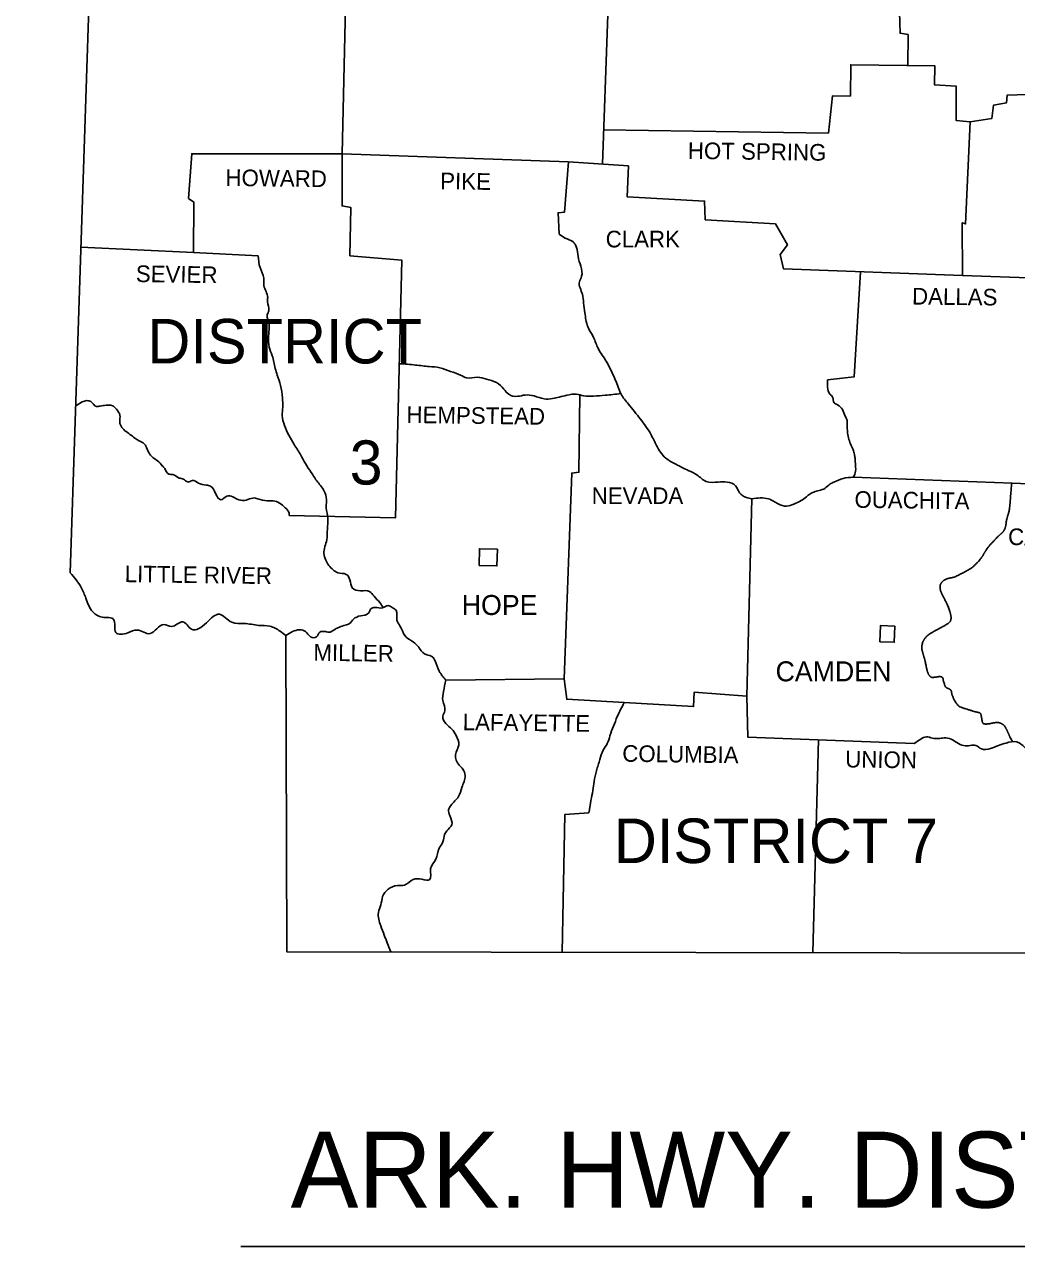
# Model space of a CAD drawing. Extents: x -819161 to 80911, y -6604 to 768454.
# Drawn here: x 60665 to 62056, y 6165 to 7879 of the extents above; entities that cross this region are included whole.
import ezdxf

# ---------------------------------------------------------------- set-up
doc = ezdxf.new("R2010")
doc.units = 0
doc.layers.add('Default', color=7, linetype='Continuous')

msp = doc.modelspace()

# ---------------------------------------------------------------- linework, layer by layer
at = {"layer": 'Default'}
for p, q in [((60745.8, 7349.6), (60736.7, 7343.9)), ((60968.3, 6164.9), (63373.8, 6164.9))]:
    msp.add_line(p, q, dxfattribs=at)
for points in [[(60664.8, 9505.7), (60778.1, 8595.4), (60729, 7109.7)], [(61270.5, 8258.8), (61269.8, 8034.6), (61242.1, 8034), (61244.6, 8017.8), (61218.2, 8018.1), (61217.6, 8005.9), (61191.7, 8005.9), (61192.3, 7997.5), (61154.4, 7996.3), (61153.4, 7963), (61116.4, 7966.4), (61110.2, 7696.9)], [(61891.6, 8113.9), (61713, 8119.2), (61708, 8048.9), (61488.6, 8050.1), (61475.1, 7682.7)], [(61708, 8048.9), (61780.5, 8042.7), (61782.7, 7973.6), (61773.7, 7970.8), (61772.4, 7934.1), (61844, 7928.8), (61844, 7898.6), (61891.6, 7896.1), (61892.6, 7866.2), (61903.8, 7864.3), (61903.4, 7821)], [(61476.9, 7730.9), (61792, 7726.2), (61798, 7778.5), (61822.9, 7778.1), (61823.5, 7822), (61941.4, 7820.5), (61940.8, 7794), (61971.3, 7791.8), (61971, 7743.9), (61990.9, 7742)], [(61990.9, 7742), (62021.4, 7746.7), (62023.6, 7765.4), (62041.6, 7768.5), (62042.9, 7779.4), (62170.5, 7783.4), (62175.5, 7816.4), (62306.2, 7814.6)], [(61990.9, 7742), (61984.4, 7598.9), (61979.7, 7600.4), (61980, 7526.5)], [(61427.6, 7686), (61110.2, 7696.9), (60899.5, 7697.2), (60894.8, 7634.7), (60902.3, 7629.4), (60902, 7559), (60744.1, 7566.3)], [(61110.2, 7696.9), (61110.2, 7624.1), (61122.3, 7621.9), (61121.1, 7554.1), (61193.9, 7548.2), (61184.9, 7186.5), (61036.1, 7190)], [(61414.6, 7584.3), (61413, 7614.4), (61422, 7615.1), (61427.6, 7686), (61511.6, 7680.1), (61509.8, 7636.9), (61618.4, 7630.9), (61619.3, 7604.8), (61717.7, 7598.9), (61734.5, 7569.3), (61724.2, 7555.9), (61729.2, 7535.7), (61980, 7526.5)], [(60902, 7559), (60992.5, 7554.1)], [(61836.9, 7531.8), (61828.2, 7384.5), (61790.8, 7380.1)], [(61980, 7526.5), (62086.1, 7522.6)], [(61443.5, 7359.2), (61442.2, 7250.6), (61432.3, 7249.4), (61421.4, 6960.9)], [(61826.8, 7243.6), (62049.7, 7235.4), (62225.3, 7228.5)], [(61684.7, 7213.3), (61677.5, 6936.9), (61603.8, 6942.2), (61603.1, 6922), (61505.8, 6927.6)], [(61031.4, 7021.6), (61032.7, 6578.4), (63039.7, 6575)], [(61505.8, 6927.6), (61425.1, 6932.3), (61421.4, 6960.9), (61255.5, 6959.3)], [(61912.5, 6870.3), (61679.1, 6879.1), (61677.5, 6936.9)], [(61778.4, 6875.3), (61770.1, 6577.2)], [(61456.3, 6772.9), (61422.6, 6770.8), (61419, 6577.8)]]:
    msp.add_lwpolyline(points, dxfattribs=at)
for points in [[(61302.2, 7119.9), (61302.8, 7143.3), (61328, 7142.6), (61327.4, 7119.3)], [(61864.3, 7012.9), (61864.9, 7035.6), (61885.1, 7035), (61884.5, 7012.3)]]:
    msp.add_lwpolyline(points, close=True, dxfattribs=at)
for points in [[(61414.6, 7584.3), (61423, 7579), (61433.5, 7574), (61439.1, 7565.9), (61441, 7553.1), (61445, 7539.4), (61446, 7525.4), (61442.9, 7517.7), (61447.2, 7500.2), (61448.8, 7488.1), (61450.7, 7474.1), (61454.7, 7454.8), (61461.9, 7441.7), (61468.4, 7425.9), (61479.3, 7408.4), (61488.9, 7390.1), (61493.3, 7380.4), (61501.4, 7360.2), (61511.6, 7346.2), (61528.5, 7325.3), (61543.1, 7303.9), (61551.2, 7288), (61563.9, 7270.6), (61578.2, 7261.8), (61596.3, 7252.8), (61607.8, 7246.9), (61620.6, 7237.6), (61637.7, 7236.9), (61650.1, 7236.9), (61662, 7231.7), (61667.3, 7222), (61677.2, 7215.2), (61684.7, 7213.3)], [(60992.5, 7554.1), (60995.3, 7537.6), (61000.3, 7522.9), (61000.6, 7512.4), (61005.9, 7495.9), (61005.6, 7490), (61007.5, 7477.5), (61005.3, 7471.3), (61007.8, 7458.2), (61007.5, 7447.9), (61007.2, 7439.9), (61008.1, 7426.2), (61012.2, 7414), (61016.5, 7396.3), (61019.3, 7386.6), (61024, 7372.3), (61026.5, 7354.9), (61027.1, 7342.1), (61026.2, 7330), (61029.6, 7316.3), (61035.5, 7302.6), (61043, 7289.5), (61052.3, 7274.6), (61058.8, 7262.8), (61066.9, 7250.3), (61073.5, 7240.1), (61083.7, 7226.7), (61088.1, 7215.8), (61088.1, 7200.8), (61090.3, 7186.2), (61089.6, 7170.7), (61088.7, 7156), (61084.7, 7136.7), (61087.2, 7127.4), (61097.7, 7113.7), (61104.3, 7109.7), (61115.8, 7107.5), (61121.1, 7099.7), (61124.5, 7088.5), (61136, 7084.5), (61148.8, 7083.5), (61155, 7076.7), (61163.1, 7068), (61168, 7060.7)], [(61190.3, 7402.8), (61213.2, 7401), (61232.5, 7398.8), (61247.1, 7397.2), (61262.4, 7391.9), (61276.4, 7386.9), (61285.1, 7382.9), (61299.7, 7383.8), (61312.5, 7381.3), (61326.5, 7376.4), (61337.1, 7367), (61343.9, 7359.9), (61356.4, 7357.1), (61366.9, 7358.9), (61379.4, 7357.7), (61393.4, 7353.6), (61405.2, 7354), (61414.6, 7356.1), (61425.4, 7358.6), (61438.8, 7360.2), (61449.1, 7357.7), (61462.8, 7357.4), (61479, 7358.6), (61500.9, 7361)], [(61790.8, 7380.1), (61790.8, 7369.8), (61794.2, 7360.2), (61798, 7355.8), (61799.8, 7348.4), (61804.8, 7345.2), (61811.7, 7338.4), (61815.7, 7329.4), (61818.2, 7323.2), (61818.5, 7315.4), (61818.8, 7307.9), (61820.1, 7298.9), (61826.6, 7282.1), (61828.5, 7275.5), (61829.4, 7269.9), (61830, 7260.6), (61829.7, 7249.7), (61826.8, 7243.6)], [(60745.8, 7349.6), (60757.9, 7349.9), (60765.7, 7342.8), (60771, 7343.4), (60779.4, 7344.6), (60788.1, 7344), (60793.7, 7339), (60798.7, 7330.6), (60798.4, 7322.2), (60798.7, 7318.8), (60802.7, 7311.9), (60809.2, 7306.3), (60816.4, 7301.1), (60822.6, 7296.4), (60833.8, 7289.5), (60835.1, 7287.4), (60839.1, 7278.3), (60844.7, 7271.5), (60851.3, 7266.8), (60858.4, 7259.4), (60861.5, 7255.9), (60867.1, 7248.1), (60873, 7247.5), (60881.8, 7242.5), (60887.7, 7241), (60893.9, 7236.9), (60900.4, 7239.1), (60908.8, 7235.4), (60919.7, 7232.6), (60925.9, 7231), (60932.8, 7220.8), (60940.3, 7212), (60948.7, 7217), (60965.5, 7212), (60975.7, 7211.7), (60985.1, 7214.5), (60992.2, 7213.6), (61005.3, 7210.5), (61013.4, 7210.5), (61022.4, 7207.4), (61030.5, 7200.8), (61035.8, 7193.4), (61036.1, 7190)], [(61799.8, 7236.6), (61794.2, 7234.1), (61787.4, 7228.2), (61779, 7225.1), (61771.5, 7222.9), (61761.2, 7216.4), (61754.1, 7210.8), (61743.5, 7206.1), (61733.5, 7203), (61721.4, 7206.4), (61714.9, 7210.2), (61708, 7213.3), (61684.7, 7213.3)], [(61799.8, 7236.6), (61812.6, 7241.9), (61826.8, 7243.6)], [(60729, 7109.7), (60744.5, 7089.1), (60751, 7073.9), (60760.7, 7054.9), (60774.1, 7047.4), (60789.9, 7044.3), (60793.1, 7025.9), (60809.6, 7025.3), (60822.9, 7029.4), (60841, 7024.4), (60860.3, 7037.1), (60871.2, 7034.3), (60886.7, 7040.9), (60899.2, 7030.6), (60920, 7039.6), (60938.4, 7051.5), (60955.8, 7040.3), (60972.9, 7038.7), (60993.2, 7035.9), (61009, 7034.7), (61023.4, 7027.8), (61031.4, 7021.6)], [(61031.4, 7021.6), (61050.4, 7029.7), (61059.1, 7027.2), (61066, 7020), (61074.4, 7019.7), (61078.8, 7026.3), (61086.8, 7027.2), (61093.4, 7026.6), (61100.5, 7030.6), (61106.5, 7033.4), (61114.5, 7036.2), (61120.8, 7038.7), (61126.1, 7044.6), (61136.3, 7049.3), (61147.5, 7053.3), (61150.6, 7058.9), (61156.2, 7061.1), (61167.1, 7060.5), (61174.6, 7063.6), (61180.5, 7060.8), (61185.8, 7057.1), (61187.1, 7043.1), (61191.4, 7035.3), (61198.3, 7021.6), (61207.3, 7014.4), (61216, 7007.3), (61219.1, 7002.9), (61228.8, 6994.5), (61236.8, 6992), (61240.6, 6986.1), (61246.5, 6971.5), (61255.5, 6959.3)], [(61255.5, 6959.3), (61252.4, 6943.2), (61251.5, 6930.4), (61254.3, 6916.1), (61251.5, 6908.6), (61255.8, 6898.3), (61264.2, 6890.3), (61270.1, 6881.5), (61273.9, 6868.5), (61269.2, 6854.5), (61274.5, 6839.8), (61279.5, 6834.2), (61282.6, 6825.2), (61278.2, 6808.7), (61273.6, 6796), (61262.7, 6783.5), (61259.6, 6777.3), (61261.1, 6769.2), (61263.9, 6756.1), (61260.8, 6752.1), (61254, 6742.7), (61251.5, 6732.5), (61246.5, 6723.4), (61241.5, 6707.9), (61234.4, 6694.5), (61233.1, 6679.6), (61221.9, 6679.9), (61209.8, 6679.6), (61197.9, 6671.8), (61187.7, 6671.2), (61174.9, 6665.9), (61167.1, 6655.6), (61164.6, 6644.1), (61161.2, 6633.2), (61164.3, 6614.5), (61169.3, 6601.5), (61173.4, 6590.9), (61178.6, 6578.2)], [(61456.3, 6772.9), (61459.1, 6790.4), (61461.9, 6804.4), (61463.7, 6817.1), (61466.8, 6832.1), (61471.8, 6847.9), (61476.2, 6861), (61482.1, 6870.3), (61485.8, 6881.2), (61490.8, 6894.6), (61496.1, 6908), (61505.8, 6927.6)], [(61912.5, 6870.3), (61921.5, 6876.6), (61929.6, 6879.7), (61938, 6877.8), (61946.4, 6877.2), (61954.2, 6878.1), (61964.1, 6876.3), (61972.2, 6871.6), (61981.6, 6867.5), (61990.9, 6867.5), (61999, 6867.5), (62006.5, 6862.6), (62019.2, 6863.2), (62030.4, 6867.5), (62041.3, 6871), (62056.3, 6872.5), (62069, 6863.5), (62078.7, 6855.7), (62086.1, 6847), (62091.7, 6837), (62098, 6831.4), (62107.6, 6827.7), (62115.4, 6825.8), (62124.4, 6823.3), (62129.4, 6820.9), (62133.8, 6810.9), (62140.9, 6796.3), (62154.9, 6791.6), (62171.4, 6798.1), (62185.4, 6801.9), (62195.4, 6805), (62201, 6807.2), (62206.6, 6808.1), (62205.3, 6809), (62211.6, 6810.6), (62217.8, 6806.2), (62221.5, 6800.3), (62228.1, 6791.3), (62234, 6783.8), (62239.9, 6781.3), (62246.4, 6784.4), (62254.2, 6781.6), (62261.4, 6779.2), (62269.8, 6776.7), (62276.6, 6776.4), (62286.3, 6774.2), (62293.1, 6770.1), (62299.6, 6766.1), (62306.5, 6759.2), (62313, 6748), (62315.2, 6739.3), (62322.7, 6730.6), (62330.1, 6730.6), (62340.1, 6716.6), (62344.1, 6711), (62352.2, 6701.4), (62358.1, 6701), (62369.9, 6699.2)]]:
    msp.add_spline(points, degree=3, dxfattribs=at)
msp.add_open_spline([(62049, 7235.4), (62048.1, 7224.2), (62047.2, 7213), (62046.3, 7201.8), (62046.1, 7198.9), (62045.4, 7196.1), (62044.6, 7193.3), (62044.2, 7191.9), (62043.8, 7190.5), (62043.4, 7189.2), (62043, 7187.8), (62042.6, 7186.4), (62042.3, 7185), (62041.6, 7182.4), (62041.4, 7179.7), (62040.9, 7177.1), (62040.7, 7175.7), (62040.4, 7174.4), (62040.1, 7173.1), (62039.9, 7172.5), (62039.7, 7171.9), (62039.4, 7171.3), (62039.3, 7170.9), (62039.1, 7170.6), (62039, 7170.3), (62038.9, 7170), (62038.7, 7169.7), (62038.5, 7169.4), (62038, 7168.5), (62037.4, 7167.7), (62036.7, 7166.9), (62036.1, 7166.2), (62035.4, 7165.5), (62034.6, 7164.8), (62033.9, 7164.1), (62033.1, 7163.5), (62032.3, 7162.8), (62031.6, 7162.1), (62030.8, 7161.4), (62030.1, 7160.7), (62028.7, 7159.2), (62027.2, 7157.7), (62025.8, 7156.2), (62024.3, 7154.7), (62022.9, 7153.2), (62021.4, 7151.7), (62018.5, 7148.7), (62016.1, 7145.4), (62013.6, 7142), (62012.9, 7141.1), (62012.3, 7140.1), (62011.7, 7139.1), (62011.1, 7138.1), (62010.5, 7137.1), (62009.9, 7136.1), (62009.3, 7135.1), (62008.7, 7134.1), (62008.1, 7133.1), (62007.5, 7132.1), (62006.8, 7131.2), (62006.2, 7130.2), (62004, 7127.3), (62001.6, 7124.7), (61999, 7122.1), (61996.2, 7119.3), (61993.3, 7116.7), (61990, 7114.6), (61986.8, 7112.7), (61983.6, 7111), (61980.3, 7109.3), (61977, 7107.6), (61973.8, 7105.9), (61970.4, 7104.4), (61969.5, 7103.9), (61968.5, 7103.6), (61967.5, 7103.3), (61966.5, 7103.1), (61965.5, 7102.9), (61964.5, 7102.7), (61963.5, 7102.5), (61962.5, 7102.3), (61961.5, 7102.1), (61960.5, 7101.9), (61959.5, 7101.6), (61958.5, 7101.3), (61957, 7100.7), (61955.5, 7100), (61954.1, 7099.1), (61953.4, 7098.7), (61952.8, 7098.2), (61952.2, 7097.6), (61951.8, 7097.3), (61951.6, 7097), (61951.3, 7096.7), (61951, 7096.4), (61950.7, 7096), (61950.5, 7095.7), (61949.8, 7094.7), (61949.3, 7093.6), (61949, 7092.5), (61948.6, 7091.3), (61948.5, 7090.1), (61948.6, 7089), (61948.8, 7086.7), (61949.2, 7084.4), (61950.1, 7082.3), (61950.8, 7080.7), (61951.5, 7079.2), (61952.3, 7077.7), (61953.1, 7076.2), (61953.9, 7074.7), (61954.7, 7073.1), (61955.5, 7071.6), (61956.3, 7070.1), (61957.1, 7068.6), (61957.9, 7067.1), (61958.5, 7065.5), (61959.2, 7063.9), (61960.3, 7061), (61961.3, 7058.1), (61962.3, 7055.2), (61962.6, 7054.3), (61962.8, 7053.4), (61963.1, 7052.5), (61963.3, 7051.6), (61963.6, 7050.7), (61963.7, 7049.8), (61963.9, 7048.9), (61964, 7047.9), (61964, 7047), (61964, 7046.6), (61964, 7046.1), (61964, 7045.6), (61964, 7045.2), (61963.9, 7044.8), (61963.8, 7044.3), (61963.6, 7043.1), (61963.1, 7042), (61962.3, 7041), (61961.5, 7039.9), (61960.6, 7039.1), (61959.5, 7038.4), (61956.7, 7036.6), (61953.9, 7035), (61951.1, 7033.4), (61947.6, 7031.5), (61944, 7029.7), (61940.5, 7027.8), (61937.3, 7026.1), (61934.4, 7024.1), (61931.5, 7021.9), (61929.9, 7020.7), (61928.6, 7019.4), (61927.4, 7017.9), (61926.8, 7017.1), (61926.4, 7016.3), (61925.9, 7015.5), (61925.4, 7014.7), (61925, 7013.8), (61924.6, 7012.9), (61923.8, 7010.8), (61923.3, 7008.6), (61923.2, 7006.5), (61923.1, 7004.4), (61923.2, 7002.2), (61923.7, 7000.1), (61924, 6998.9), (61924.3, 6997.7), (61924.7, 6996.5), (61925, 6995.2), (61925.4, 6994), (61925.7, 6992.8), (61926.1, 6991.6), (61926.4, 6990.4), (61926.8, 6989.2), (61927.1, 6987.9), (61927.4, 6986.7), (61927.7, 6985.5), (61928.4, 6982.5), (61929, 6979.5), (61929.6, 6976.5), (61929.9, 6975.2), (61930.2, 6973.9), (61930.5, 6972.6), (61930.8, 6971.3), (61931.3, 6970.1), (61931.7, 6968.8), (61932.2, 6967.6), (61932.9, 6966.5), (61933.7, 6965.5), (61934.1, 6965), (61934.5, 6964.5), (61935.1, 6964.1), (61935.3, 6963.9), (61935.6, 6963.7), (61935.9, 6963.6), (61936.2, 6963.4), (61936.4, 6963.2), (61936.8, 6963.1), (61937.2, 6962.9), (61937.6, 6962.8), (61938.1, 6962.8), (61938.5, 6962.8), (61939, 6962.8), (61939.4, 6962.9), (61939.9, 6963), (61940.3, 6963.2), (61940.7, 6963.2), (61941.2, 6963.3), (61941.6, 6963.4), (61942.1, 6963.4), (61942.5, 6963.4), (61942.9, 6963.4), (61943.3, 6963.5), (61943.7, 6963.5), (61944.1, 6963.6), (61944.5, 6963.7), (61945.4, 6963.8), (61946.2, 6964), (61947, 6964.1), (61947.9, 6964.2), (61948.7, 6964.2), (61949.5, 6964), (61950, 6963.9), (61950.4, 6963.8), (61950.8, 6963.6), (61951, 6963.5), (61951.2, 6963.3), (61951.4, 6963.2), (61951.6, 6963.1), (61951.8, 6963), (61952, 6962.8), (61952.4, 6962.4), (61952.6, 6961.9), (61952.8, 6961.4), (61952.9, 6960.9), (61952.8, 6960.4), (61952.9, 6960), (61953.1, 6959.1), (61953.3, 6958.3), (61953.6, 6957.5), (61954.2, 6955), (61955, 6952.7), (61956.1, 6950.3), (61956.4, 6949.6), (61957, 6948.9), (61957.7, 6948.5), (61958.5, 6948.1), (61959.3, 6947.7), (61960.1, 6947.4), (61960.9, 6947), (61961.7, 6946.6), (61962.5, 6946.2), (61963.2, 6945.8), (61963.8, 6945.2), (61964.1, 6944.4), (61964.4, 6944), (61964.5, 6943.5), (61964.6, 6943), (61964.6, 6942.6), (61964.7, 6942.1), (61964.8, 6941.6), (61964.9, 6941.1), (61964.9, 6940.7), (61965, 6940.2), (61965.1, 6939.7), (61965.2, 6939.3), (61965.4, 6938.8), (61966, 6937), (61966.8, 6935.2), (61967.6, 6933.4), (61968.3, 6931.6), (61969.3, 6929.9), (61970.4, 6928.2), (61972.4, 6925.2), (61974.9, 6922.4), (61978.2, 6921.1), (61980.2, 6920.2), (61982.3, 6919.5), (61984.4, 6918.9), (61988.5, 6917.6), (61992.7, 6916.4), (61996.8, 6915.2), (61999, 6914.5), (62001.2, 6914.2), (62003.4, 6913.6), (62003.7, 6913.5), (62004, 6913.4), (62004.3, 6913.2), (62005.2, 6912.5), (62005.9, 6911.6), (62006.1, 6910.5), (62006.4, 6908.8), (62006.7, 6907), (62007, 6905.3), (62007.4, 6903.6), (62007.7, 6901.9), (62008, 6900.2), (62008.2, 6899.5), (62008.5, 6899), (62009.1, 6898.5), (62009.6, 6898), (62010.2, 6897.8), (62010.8, 6897.7), (62012.3, 6897.6), (62013.7, 6897.6), (62015.2, 6897.8), (62016.6, 6897.9), (62018.1, 6898.1), (62019.5, 6898.3), (62020.6, 6898.6), (62021.6, 6898.8), (62022.7, 6899), (62023.7, 6899.2), (62024.7, 6899.4), (62025.8, 6899.6), (62027.6, 6899.9), (62029.6, 6899.8), (62031.4, 6899.4), (62032.4, 6899.2), (62033.3, 6898.9), (62034.2, 6898.5), (62034.7, 6898.2), (62035.1, 6898), (62035.6, 6897.7), (62036.1, 6897.4), (62036.5, 6897.1), (62037, 6896.8), (62038.1, 6895.9), (62039.1, 6894.9), (62039.8, 6893.7), (62040.4, 6892.6), (62041.1, 6891.4), (62041.6, 6890.3), (62042.1, 6889.3), (62042.6, 6888.4), (62043, 6887.5), (62043.4, 6886.5), (62043.8, 6885.6), (62044.3, 6884.7), (62044.7, 6883.7), (62045.1, 6882.8), (62045.5, 6881.8), (62045.9, 6880.9), (62046.4, 6880), (62046.9, 6879.1), (62048, 6877.1), (62048.9, 6875), (62050.3, 6873.3)], degree=3, dxfattribs=at)

# ---------------------------------------------------------------- texts
for s, height, rotation, p in [('HOT SPRING', 23.34, 359.1956, (61594.9, 7690.1)), ('HOWARD', 23.34, 359.303, (60946.6, 7652.1)), ('PIKE', 23.34, 359.1737, (61247.6, 7647.5)), ('SEVIER', 23.34, 359.1815, (60820.9, 7517.4)), ('DALLAS', 23.34, 359.2802, (61909.2, 7485.9)), ('HEMPSTEAD', 23.34, 359.2571, (61200.4, 7319.8)), ('OUACHITA', 23.34, 359.2027, (61828.5, 7200.9)), ('CALHOUN', 23.34, 359.2686, (62043.9, 7148.6)), ('LITTLE RIVER', 23.341, 359.2076, (60805.3, 7096.6)), ('MILLER', 23.34, 359.1885, (61069.9, 6986.4)), ('LAFAYETTE', 23.34, 359.2511, (61279.2, 6889)), ('COLUMBIA', 23.34, 359.2105, (61502.9, 6844.8)), ('UNION', 23.34, 359.2015, (61815.5, 6836.8))]:
    msp.add_text(s, height=height, rotation=rotation, dxfattribs=at).set_placement(p)
for s, height, p in [('CLARK', 23.34, (61479.8, 7565.9)), ('DISTRICT', 62.43, (60837.2, 7403.2)), ('3', 61.9, (61120.9, 7233.4)), ('NEVADA', 23.34, (61460.2, 7206.1)), ('HOPE', 28.01, (61278, 7050.5)), ('CAMDEN', 28.01, (61718, 6957.5)), ('DISTRICT 7', 62.43, (61491.2, 6702.7)), ('ARK. HWY. DIST. NO. 2, 6 & 8', 106.498, (61038.1, 6219.5))]:
    msp.add_text(s, height=height, dxfattribs=at).set_placement(p)

doc.saveas('drawing.dxf')
